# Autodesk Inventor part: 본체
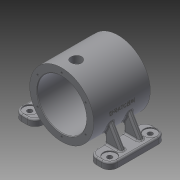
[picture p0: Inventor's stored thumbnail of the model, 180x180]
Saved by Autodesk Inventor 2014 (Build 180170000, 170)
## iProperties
Created: 2024-02
Part Number: 본체
Material: 알루미늄 6061
Document SubType Name: Modeling
Designer: mdu-01
Density: 2.71 g/cm^3
Mass: 1628.82 g
Surface Area: 1087.98 cm^2
Volume: 601.04 cm^3
Appearance: 기본값
Author: mdu-01
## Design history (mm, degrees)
sketch "스케치1"
  geometry: C1 r 12 at (0, 11) reference; C2 r 60 at (0, 11); C3 r 46 at (0, 11); C4 r 14 at (0, -20) reference; A1 r 16 centre (0, -20) between (-3.969, -4.5) and (3.969, -4.5) reference; 1 further point
  constraints: 2 centre point, 2 coincident
  dimensions: "d0" = 120 diameter of C2; "d1" = 14 radial gap between concentric circles of C2 C3
extrude "돌출1" new body sketch "스케치1" distance "d2" = 106; taper "d3" = 0 deg
sketch "스케치2"
  geometry: L1 (58, 89)-(67, 89) reference; L2 (71, 0)-(71, 106) reference; L3 (53, 94)-(53, 64) reference; L4 (53, 79)-(71, 79); L5 (67, 89)-(71, 89); L6 (53, 94)-(58, 94); L7 (58, 94)-(58, 89); L8 (53, 79)-(43, 79); L9 (43, 79)-(43, 94); L10 (43, 94)-(53, 94); 1 further point
  constraints: 16 end point, 4 perpendicular, 2 parallel, 2 point on line, 1 horizontal, 1 midpoint, 1 vertical, 2 other
  dimensions: "d5" = 10 distance between parallel lines of L9 L3
revolve "회전1" sketch "스케치2" stored, may be unused: angle "d4" = 90 deg
sketch "스케치3"
  geometry: C1 r 60 at (0, 0) reference; 2 further points
  constraints: 2 vertical alignment, 2 other
  dimensions: "d6" = 8 dimension on C1
hole "구멍1" sketch "스케치3" at (0, 52) diameter "d7" = 3.242; stored, may be unused: countersink angle "d11" = 90 deg, drill point angle "d13" = 118 deg; dims "d8" = 8, "d9" = 8, "d10" = 4.6, "d12" = 10
hole "구멍2" diameter "d16" = 3.242; stored, may be unused: countersink angle "d20" = 90 deg, drill point angle "d22" = 118 deg; dims "d14" = 10, "d15" = 10, "d17" = 8, "d18" = 8, "d19" = 4.6, "d21" = 10
sketch "스케치4"
  geometry: L1 (50, -54)-(90, -54); L2 (90, -54)-(90, -42); L3 (90, -42)-(50, -42); L4 (50, -42)-(50, -54); C1 r 60 at (0, 11) reference; 1 further point
  constraints: 8 end point, 2 parallel, 1 horizontal, 1 perpendicular
  dimensions: "d26" = 12 distance between parallel lines of L1 L3; "d28" = 65 distance from line of L1 C1.centre; "d29" = 50 distance from line of L4 C1.centre; "d30" = 40 distance between parallel lines of L2 L4
extrude "돌출2" join sketch "스케치4" distance "d31" = 106; taper "d32" = 0 deg
node "작업 평면1"
sketch "스케치5"
  geometry: L1 (-90, -42)-(-50, -42) reference; L2 (-50, -42)-(-50, -22.166); L3 (-80, -42)-(-58.084, -4.041); A1 r 60 centre (0, 11) between (-50, -22.166) and (-58.084, -4.041) reference; 1 further point
  constraints: 4 end point, 2 point on circle, 1 perpendicular, 1 point on line
  dimensions: "d33" = 10 distance of L3.start L1.start; "d34" = 60 deg angle of L1 L3
extrude "돌출3" join sketch "스케치5" distance "d37" = 9; taper "d38" = 0 deg
node "작업 평면3"
fillet "모깎기1" dims "d39" = 15
sketch "스케치6"
  geometry: A1 r 15 centre (25, 16) between (40, 16) and (25, 31) reference; A2 r 15 centre (25, -60) between (25, -75) and (40, -60) reference; 1 further point
hole "구멍3" sketch "스케치6" at (25, -60), (25, 16) diameter "d40" = 9; stored, may be unused: countersink angle "d44" = 90 deg, drill point angle "d46" = 118 deg; dims "d41" = 8, "d42" = 24, "d43" = 2, "d45" = 10
fillet "모깎기2" dims "d47" = 3
fillet "모깎기3" dims "d48" = 3
fillet "모깎기4" dims "d49" = 3
fillet "모깎기5" dims "d50" = 3
sketch "스케치7"
  geometry: L1 (71, 106)-(-49, 106) reference; 3 further points
  constraints: 1 midpoint, 1 vertical alignment, 1 other
  dimensions: "d51" = 53 distance from line of point (11, 53) L1
feature "엠보싱1" sketch "스케치7" dims "d0" = 120, "d1" = 14, "d52" = 0.5, "d53" = 0
chamfer "모따기1" distance "d54" = 1; stored, may be unused: second distance "d55" = 2, angle "d56" = 45 deg
node "솔리드1"
pattern_circular "원형 패턴1" dims angle "d24" = 360 deg
mirror "대칭1"
mirror "대칭2"
node "참조1"
node "참조2"
node "참조3"
node "참조4"
